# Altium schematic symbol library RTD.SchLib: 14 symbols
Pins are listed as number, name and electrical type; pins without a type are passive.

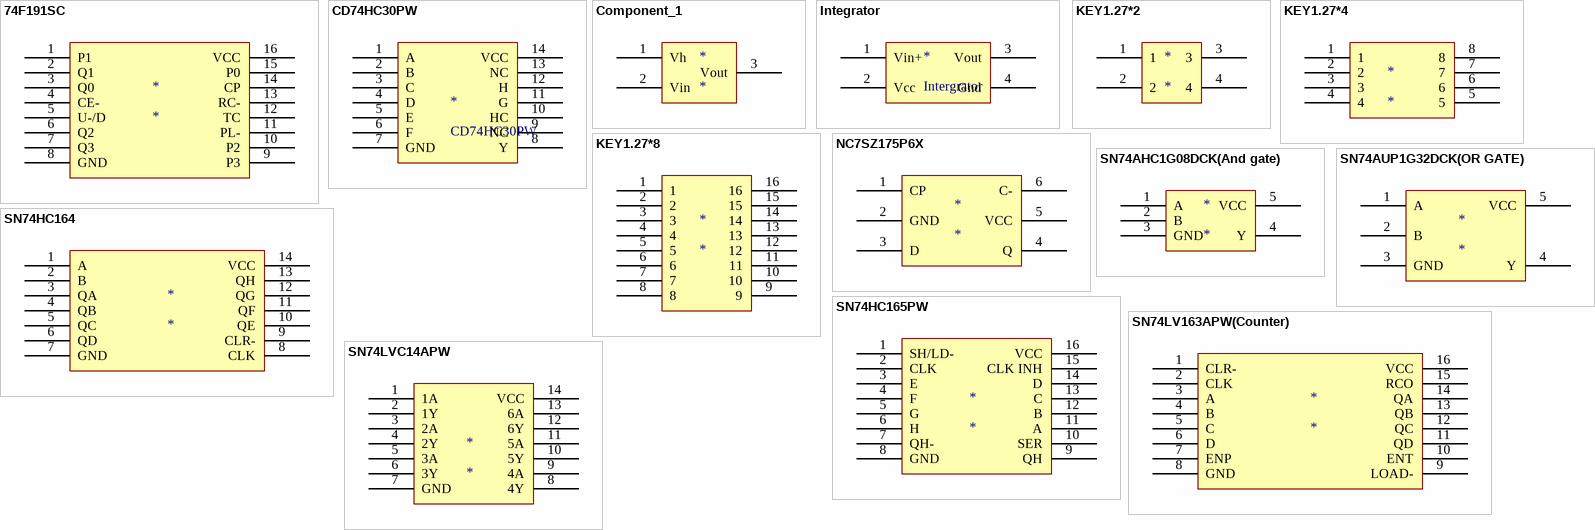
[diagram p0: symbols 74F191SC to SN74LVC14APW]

## 74F191SC
designator *
pins: 1 P1, 2 Q1, 3 Q0, 4 CE-, 5 U-/D, 6 Q2, 7 Q3, 8 GND, 9 P3, 10 P2, 11 PL-, 12 TC, 13 RC-, 14 CP, 15 P0, 16 VCC

## CD74HC30PW
designator *
pins: 1 A, 2 B, 3 C, 4 D, 5 E, 6 F, 7 GND, 8 Y, 9 NC, 10 HC, 11 G, 12 H, 13 NC, 14 VCC

## Component_1
designator *
pins: 1 Vh, 2 Vin, 3 Vout

## Integrator
designator *, comment Intergrator
pins: 1 Vin+, 2 Vcc, 3 Vout, 4 Gnd

## KEY1.27*2
designator *
pins: 1, 2, 3, 4

## KEY1.27*4
designator *
pins: 1, 2, 3, 4, 5, 6, 7, 8

## KEY1.27*8
designator *
pins: 1, 2, 3, 4, 5, 6, 7, 8, 9, 10, 11, 12, 13, 14, 15, 16

## NC7SZ175P6X
designator *
pins: 1 CP, 2 GND, 3 D, 4 Q, 5 VCC, 6 C-

## SN74AHC1G08DCK(And gate)
designator *
pins: 1 A, 2 B, 3 GND, 4 Y, 5 VCC

## SN74AUP1G32DCK(OR GATE)
designator *
pins: 1 A, 2 B, 3 GND, 4 Y, 5 VCC

## SN74HC164
designator *
pins: 1 A, 2 B, 3 QA, 4 QB, 5 QC, 6 QD, 7 GND, 8 CLK, 9 CLR-, 10 QE, 11 QF, 12 QG, 13 QH, 14 VCC

## SN74HC165PW
designator *
pins: 1 SH/LD-, 2 CLK, 3 E, 4 F, 5 G, 6 H, 7 QH-, 8 GND, 9 QH, 10 SER, 11 A, 12 B, 13 C, 14 D, 15 CLK INH, 16 VCC

## SN74LV163APW(Counter)
designator *
pins: 1 CLR-, 2 CLK, 3 A, 4 B, 5 C, 6 D, 7 ENP, 8 GND, 9 LOAD-, 10 ENT, 11 QD, 12 QC, 13 QB, 14 QA, 15 RCO, 16 VCC

## SN74LVC14APW
designator *
pins: 1 1A, 2 1Y, 3 2A, 4 2Y, 5 3A, 6 3Y, 7 GND, 8 4Y, 9 4A, 10 5Y, 11 5A, 12 6Y, 13 6A, 14 VCC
